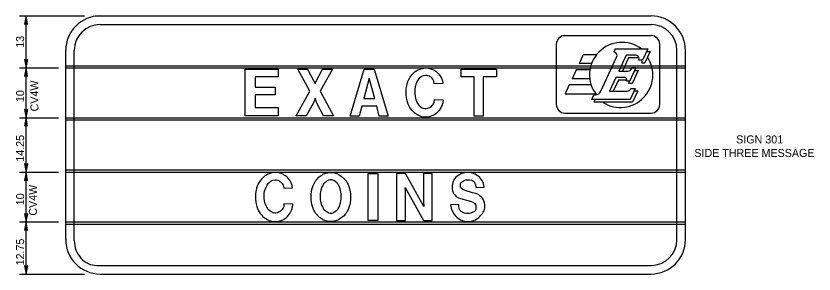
# Model space of a CAD drawing. Extents: x 319706 to 320346, y 1621790 to 1622121.
# Drawn here: x 319881.2 to 320020.8, y 1622067.9 to 1622113.1 of the extents above; entities that cross this region are included whole.
import ezdxf

# ---------------------------------------------------------------- set-up
doc = ezdxf.new("R2010")
doc.units = 0
for name, color, linetype in [('1', 7, 'Continuous'), ('40', 7, 'Continuous'), ('52', 7, 'Continuous'), ('SignPanel', 7, 'Continuous')]:
    doc.layers.add(name, color=color, linetype=linetype)

msp = doc.modelspace()

# ---------------------------------------------------------------- linework, layer by layer
at = {"layer": '1'}
for p, q in [((319881.84, 1622113.08), (319893.22, 1622113.08)), ((319882.98, 1622104), (319882.98, 1622113.08)), ((319881.84, 1622104), (319888.63, 1622104)), ((319882.98, 1622095.27), (319882.98, 1622104)), ((319881.84, 1622095.27), (319888.63, 1622095.27)), ((319882.98, 1622085.75), (319882.98, 1622095.27)), ((319881.84, 1622085.75), (319888.63, 1622085.75)), ((319882.98, 1622077.02), (319882.98, 1622085.75)), ((319881.84, 1622077.02), (319888.63, 1622077.02)), ((319882.98, 1622067.91), (319882.98, 1622077.01)), ((319881.84, 1622067.91), (319893.22, 1622067.91))]:
    msp.add_line(p, q, dxfattribs=at)
at = {"layer": '40'}
msp.add_line((319936.28, 1622085.68), (319936.22, 1622085.68), dxfattribs=at)
for points in [[(319921.32, 1622095.58), (319921.32, 1622103.78), (319927.07, 1622103.78), (319927.07, 1622102.43), (319923.03, 1622102.43), (319923.03, 1622100.62), (319926.55, 1622100.62), (319926.55, 1622099.26), (319923.03, 1622099.26), (319923.03, 1622097.06), (319927.07, 1622097.06), (319927.07, 1622095.58), (319921.32, 1622095.58)], [(319930.23, 1622095.57), (319932.64, 1622099.9), (319930.53, 1622103.78), (319932.23, 1622103.78), (319933.34, 1622101.65), (319933.52, 1622101.19), (319933.7, 1622101.65), (319934.81, 1622103.78), (319936.57, 1622103.78), (319934.4, 1622099.9), (319936.75, 1622095.57), (319934.99, 1622095.57), (319933.81, 1622097.83), (319933.52, 1622098.67), (319933.23, 1622097.9), (319931.99, 1622095.57), (319930.23, 1622095.57)], [(319939.68, 1622095.55), (319942.14, 1622103.75), (319943.85, 1622103.75), (319946.31, 1622095.55), (319944.72, 1622095.55), (319944.31, 1622097.29), (319941.73, 1622097.29), (319941.26, 1622095.55), (319939.68, 1622095.55)], [(319955.92, 1622098.42), (319955.87, 1622097.9), (319955.75, 1622097.51), (319955.57, 1622097.13), (319955.4, 1622096.8), (319955.22, 1622096.54), (319955.1, 1622096.42), (319954.99, 1622096.29), (319954.87, 1622096.16), (319954.63, 1622095.96), (319954.46, 1622095.83), (319954.34, 1622095.77), (319954.1, 1622095.64), (319953.93, 1622095.57), (319953.69, 1622095.51), (319953.46, 1622095.45), (319952.99, 1622095.38), (319952.7, 1622095.38), (319952.23, 1622095.45), (319952.05, 1622095.51), (319951.82, 1622095.57), (319951.58, 1622095.7), (319951.35, 1622095.83), (319951.23, 1622095.9), (319951.05, 1622096.03), (319950.76, 1622096.29), (319950.52, 1622096.54), (319950.29, 1622096.8), (319950.11, 1622097.06), (319949.94, 1622097.39), (319949.82, 1622097.64), (319949.7, 1622098.03), (319949.59, 1622098.48), (319949.53, 1622098.81), (319949.47, 1622099.26), (319949.47, 1622099.84), (319949.47, 1622100.29), (319949.53, 1622100.62), (319949.59, 1622100.87), (319949.64, 1622101.2), (319949.76, 1622101.59), (319949.94, 1622101.97), (319950.17, 1622102.36), (319950.47, 1622102.75), (319950.82, 1622103.14), (319951.05, 1622103.33), (319951.35, 1622103.52), (319951.58, 1622103.65), (319952.11, 1622103.85), (319952.34, 1622103.91), (319952.81, 1622103.98), (319953.05, 1622103.98), (319953.52, 1622103.91), (319953.75, 1622103.85), (319953.93, 1622103.78), (319954.22, 1622103.65), (319954.46, 1622103.52), (319954.63, 1622103.39), (319954.87, 1622103.2), (319955.04, 1622103.01), (319955.34, 1622102.68), (319955.46, 1622102.49), (319955.63, 1622102.17), (319955.81, 1622101.71), (319955.87, 1622101.26)], [(319959.09, 1622103.76), (319965.25, 1622103.76), (319965.25, 1622102.4), (319962.96, 1622102.4), (319962.96, 1622095.55), (319961.38, 1622095.55), (319961.38, 1622102.4), (319959.09, 1622102.4), (319959.09, 1622103.76)], [(319954.34, 1622101.2), (319954.28, 1622101.65), (319954.22, 1622101.78), (319954.1, 1622102.04), (319953.93, 1622102.23), (319953.81, 1622102.36), (319953.69, 1622102.43), (319953.52, 1622102.55), (319953.34, 1622102.62), (319953.11, 1622102.68), (319952.93, 1622102.68), (319952.46, 1622102.62), (319952.17, 1622102.49), (319951.76, 1622102.17), (319951.64, 1622102.04), (319951.46, 1622101.78), (319951.29, 1622101.39), (319951.17, 1622101.13), (319951.11, 1622100.87), (319951.05, 1622100.68), (319950.99, 1622100.29), (319950.99, 1622099.97), (319950.99, 1622099.9), (319950.99, 1622099.58), (319950.99, 1622099.39), (319951.05, 1622099), (319951.11, 1622098.68), (319951.17, 1622098.42), (319951.29, 1622098.16), (319951.4, 1622097.9), (319951.64, 1622097.51), (319951.99, 1622097.19), (319952.28, 1622097), (319952.46, 1622096.93), (319952.81, 1622096.87), (319952.99, 1622096.87), (319953.28, 1622096.93), (319953.58, 1622097.06), (319953.81, 1622097.19), (319954.05, 1622097.45), (319954.22, 1622097.71), (319954.34, 1622097.97), (319954.4, 1622098.48)], [(319943.02, 1622102.2), (319942.08, 1622098.65), (319943.96, 1622098.65), (319943.02, 1622102.2)], [(319955.87, 1622101.26), (319954.34, 1622101.2)], [(319954.4, 1622098.48), (319955.92, 1622098.42)], [(319929.58, 1622082.97), (319929.52, 1622083.42), (319929.34, 1622083.88), (319929.16, 1622084.2), (319929.04, 1622084.39), (319928.75, 1622084.72), (319928.57, 1622084.91), (319928.33, 1622085.1), (319928.15, 1622085.23), (319927.92, 1622085.36), (319927.62, 1622085.49), (319927.44, 1622085.56), (319927.2, 1622085.62), (319926.73, 1622085.69), (319926.49, 1622085.69), (319926.02, 1622085.62), (319925.78, 1622085.56), (319925.25, 1622085.36), (319925.01, 1622085.23), (319924.71, 1622085.04), (319924.48, 1622084.85), (319924.12, 1622084.46), (319923.82, 1622084.07), (319923.59, 1622083.68), (319923.41, 1622083.29), (319923.29, 1622082.91), (319923.23, 1622082.58), (319923.17, 1622082.32), (319923.11, 1622082), (319923.11, 1622081.55), (319923.11, 1622080.97), (319923.17, 1622080.52), (319923.23, 1622080.19), (319923.35, 1622079.74), (319923.47, 1622079.35), (319923.59, 1622079.1), (319923.77, 1622078.77), (319923.94, 1622078.51), (319924.18, 1622078.25), (319924.42, 1622078), (319924.71, 1622077.74), (319924.89, 1622077.61), (319925.01, 1622077.54), (319925.25, 1622077.41), (319925.49, 1622077.28), (319925.72, 1622077.22), (319925.9, 1622077.16), (319926.37, 1622077.09), (319926.67, 1622077.09), (319927.15, 1622077.16), (319927.38, 1622077.22), (319927.62, 1622077.28), (319927.8, 1622077.35), (319928.04, 1622077.48), (319928.15, 1622077.54), (319928.33, 1622077.67), (319928.57, 1622077.87), (319928.69, 1622078), (319928.8, 1622078.13), (319928.92, 1622078.25), (319929.1, 1622078.51), (319929.28, 1622078.84), (319929.46, 1622079.22), (319929.58, 1622079.61), (319929.63, 1622080.13)], [(319932.84, 1622081.36), (319932.84, 1622081.55), (319932.84, 1622081.87), (319932.9, 1622082.32), (319932.96, 1622082.71), (319933.08, 1622083.04), (319933.2, 1622083.42), (319933.37, 1622083.75), (319933.49, 1622084), (319933.61, 1622084.2), (319933.79, 1622084.39), (319934.2, 1622084.84), (319934.26, 1622084.91), (319934.44, 1622085.04), (319934.62, 1622085.17), (319934.8, 1622085.3), (319934.91, 1622085.36), (319935.21, 1622085.49), (319935.45, 1622085.56), (319935.69, 1622085.62), (319936.28, 1622085.68)], [(319936.22, 1622085.68), (319936.52, 1622085.68), (319936.93, 1622085.62), (319937.17, 1622085.56), (319937.35, 1622085.49), (319937.76, 1622085.3), (319938.12, 1622085.04), (319938.41, 1622084.78), (319938.77, 1622084.39), (319938.95, 1622084.2), (319939.06, 1622084), (319939.18, 1622083.75), (319939.3, 1622083.55), (319939.42, 1622083.23), (319939.54, 1622082.84), (319939.6, 1622082.58), (319939.66, 1622082.32), (319939.72, 1622081.94), (319939.72, 1622081.74), (319939.72, 1622081.36)], [(319942.84, 1622077.3), (319942.84, 1622085.5), (319944.5, 1622085.5), (319944.5, 1622077.3), (319942.84, 1622077.3)], [(319947.8, 1622085.49), (319947.8, 1622077.29), (319949.34, 1622077.29), (319949.34, 1622082.39), (319949.28, 1622083.04), (319952.48, 1622077.29), (319954.02, 1622077.29), (319954.02, 1622085.49), (319952.48, 1622085.49), (319952.48, 1622080.65), (319952.54, 1622079.74), (319949.34, 1622085.49), (319947.8, 1622085.49)], [(319962.08, 1622085.04), (319961.9, 1622085.17), (319961.78, 1622085.24), (319961.54, 1622085.37), (319961.25, 1622085.5), (319961.07, 1622085.56), (319960.89, 1622085.62), (319960.42, 1622085.69), (319960.18, 1622085.69), (319960.06, 1622085.69), (319959.65, 1622085.62), (319959.41, 1622085.56), (319959.05, 1622085.43), (319958.82, 1622085.3), (319958.7, 1622085.24), (319958.52, 1622085.11), (319958.34, 1622084.98)], [(319928.09, 1622080.19), (319928.04, 1622079.68), (319927.92, 1622079.42), (319927.74, 1622079.16), (319927.5, 1622078.9), (319927.26, 1622078.77), (319926.97, 1622078.64), (319926.67, 1622078.58), (319926.49, 1622078.58), (319926.14, 1622078.64), (319925.96, 1622078.71), (319925.66, 1622078.9), (319925.31, 1622079.22), (319925.07, 1622079.61), (319924.95, 1622079.87), (319924.83, 1622080.13), (319924.77, 1622080.39), (319924.71, 1622080.71), (319924.65, 1622081.1), (319924.65, 1622081.29), (319924.65, 1622081.61), (319924.65, 1622081.68), (319924.65, 1622082), (319924.71, 1622082.39), (319924.77, 1622082.58), (319924.83, 1622082.84), (319924.95, 1622083.1), (319925.13, 1622083.49), (319925.31, 1622083.75), (319925.43, 1622083.88), (319925.84, 1622084.2), (319926.14, 1622084.33), (319926.61, 1622084.39), (319926.79, 1622084.39), (319927.03, 1622084.33), (319927.2, 1622084.26), (319927.38, 1622084.13), (319927.5, 1622084.07), (319927.62, 1622083.94), (319927.8, 1622083.75), (319927.92, 1622083.49), (319927.98, 1622083.36), (319928.04, 1622082.91)], [(319938.12, 1622081.48), (319938.12, 1622081.61), (319938.12, 1622081.94), (319938.06, 1622082.26), (319938, 1622082.58), (319937.88, 1622082.97), (319937.76, 1622083.29), (319937.52, 1622083.68), (319937.35, 1622083.87), (319937.05, 1622084.13), (319936.81, 1622084.26), (319936.63, 1622084.33), (319936.46, 1622084.39), (319936.34, 1622084.39), (319936.16, 1622084.39), (319935.92, 1622084.33), (319935.63, 1622084.2), (319935.45, 1622084.07), (319935.33, 1622084), (319935.21, 1622083.87), (319935.09, 1622083.75), (319935.03, 1622083.68), (319934.86, 1622083.36), (319934.68, 1622083.04), (319934.62, 1622082.78), (319934.56, 1622082.58), (319934.5, 1622082.32), (319934.44, 1622082.07), (319934.44, 1622081.87), (319934.44, 1622081.61), (319934.44, 1622081.48)], [(319958.34, 1622084.98), (319958.1, 1622084.79), (319957.81, 1622084.4), (319957.63, 1622083.94), (319957.51, 1622083.43), (319957.51, 1622082.85), (319957.57, 1622082.46), (319957.75, 1622082.01), (319957.99, 1622081.75), (319958.22, 1622081.49), (319958.64, 1622081.23), (319958.99, 1622081.1), (319960.89, 1622080.58), (319961.19, 1622080.46), (319961.48, 1622080.26), (319961.66, 1622079.94), (319961.66, 1622079.62), (319961.66, 1622079.42)], [(319958.94, 1622083.36), (319958.94, 1622083.56), (319958.99, 1622083.82), (319959.17, 1622084.01), (319959.47, 1622084.2), (319959.71, 1622084.33), (319959.88, 1622084.4), (319960.18, 1622084.4), (319960.54, 1622084.4), (319960.89, 1622084.33), (319961.13, 1622084.2), (319961.31, 1622084.07), (319961.48, 1622083.82), (319961.6, 1622083.56), (319961.66, 1622083.04)], [(319961.66, 1622083.04), (319963.08, 1622083.1), (319963.03, 1622083.43), (319962.97, 1622083.75), (319962.85, 1622084.07), (319962.73, 1622084.27), (319962.55, 1622084.59), (319962.37, 1622084.79), (319962.08, 1622085.04)], [(319928.04, 1622082.91), (319929.58, 1622082.97)], [(319963.03, 1622078.9), (319963.08, 1622078.97), (319963.14, 1622079.23), (319963.2, 1622079.55), (319963.2, 1622079.87), (319963.2, 1622080.07), (319963.14, 1622080.33), (319963.03, 1622080.71), (319962.97, 1622080.91), (319962.79, 1622081.17), (319962.61, 1622081.42), (319962.43, 1622081.56), (319962.19, 1622081.75), (319961.84, 1622081.94), (319961.37, 1622082.07), (319961.07, 1622082.14), (319959.77, 1622082.52), (319959.35, 1622082.72), (319959.17, 1622082.85), (319959.05, 1622082.98), (319958.94, 1622083.17), (319958.94, 1622083.36)], [(319939.72, 1622081.36), (319939.72, 1622080.9), (319939.66, 1622080.32), (319939.6, 1622080.06), (319939.48, 1622079.74), (319939.36, 1622079.35), (319939.24, 1622079.09), (319939.12, 1622078.9), (319938.95, 1622078.58), (319938.77, 1622078.38), (319938.59, 1622078.12), (319938.29, 1622077.87), (319938.12, 1622077.74), (319937.94, 1622077.61), (319937.64, 1622077.41), (319937.35, 1622077.28), (319937.17, 1622077.22), (319936.81, 1622077.15), (319936.46, 1622077.09), (319936.34, 1622077.09), (319936.04, 1622077.09), (319935.63, 1622077.15), (319935.45, 1622077.22), (319935.21, 1622077.28), (319935.09, 1622077.35), (319934.91, 1622077.41), (319934.8, 1622077.48), (319934.62, 1622077.61), (319934.32, 1622077.8), (319934.2, 1622077.93), (319933.73, 1622078.45), (319933.61, 1622078.58), (319933.43, 1622078.9), (319933.31, 1622079.09), (319933.2, 1622079.35), (319933.08, 1622079.74), (319933.02, 1622079.93), (319932.96, 1622080.19), (319932.9, 1622080.45), (319932.84, 1622080.84), (319932.84, 1622081.16), (319932.84, 1622081.36)], [(319934.44, 1622081.48), (319934.44, 1622081.36), (319934.44, 1622081.1), (319934.44, 1622080.9), (319934.5, 1622080.64), (319934.56, 1622080.39), (319934.62, 1622080.19), (319934.68, 1622079.93), (319934.86, 1622079.61), (319935.03, 1622079.29), (319935.09, 1622079.22), (319935.21, 1622079.09), (319935.33, 1622078.96), (319935.45, 1622078.9), (319935.63, 1622078.77), (319935.92, 1622078.64), (319936.16, 1622078.58), (319936.34, 1622078.58)], [(319936.34, 1622078.58), (319936.46, 1622078.58), (319936.63, 1622078.64), (319936.81, 1622078.71), (319937.05, 1622078.84), (319937.35, 1622079.09), (319937.52, 1622079.29), (319937.76, 1622079.68), (319937.88, 1622080), (319938, 1622080.39), (319938.06, 1622080.71), (319938.12, 1622081.03), (319938.12, 1622081.36), (319938.12, 1622081.48)], [(319929.63, 1622080.13), (319928.09, 1622080.19)], [(319958.7, 1622079.87), (319958.7, 1622080.07), (319957.22, 1622080)], [(319957.22, 1622080), (319957.28, 1622079.74), (319957.33, 1622079.49), (319957.39, 1622079.23), (319957.45, 1622079.1), (319957.51, 1622078.97), (319957.63, 1622078.77), (319957.75, 1622078.52), (319957.81, 1622078.45), (319958.05, 1622078.13), (319958.34, 1622077.87), (319958.64, 1622077.61), (319958.76, 1622077.55), (319958.99, 1622077.42), (319959.11, 1622077.35), (319959.29, 1622077.29), (319959.41, 1622077.23), (319959.65, 1622077.16), (319960.06, 1622077.1), (319960.24, 1622077.1), (319960.42, 1622077.1), (319960.83, 1622077.16), (319961.13, 1622077.23), (319961.31, 1622077.29), (319961.6, 1622077.42), (319961.84, 1622077.55), (319962.02, 1622077.68), (319962.19, 1622077.81), (319962.31, 1622077.94), (319962.49, 1622078.13), (319962.61, 1622078.26), (319962.79, 1622078.52), (319962.91, 1622078.71), (319963.03, 1622078.9)], [(319961.01, 1622078.65), (319960.77, 1622078.58), (319960.48, 1622078.52), (319960.18, 1622078.52), (319960, 1622078.52), (319959.65, 1622078.58), (319959.29, 1622078.71), (319959.11, 1622078.84), (319958.94, 1622079.03), (319958.82, 1622079.23), (319958.76, 1622079.42), (319958.7, 1622079.68), (319958.7, 1622079.87)], [(319961.66, 1622079.42), (319961.66, 1622079.23), (319961.54, 1622078.97), (319961.42, 1622078.84), (319961.01, 1622078.65)]]:
    msp.add_lwpolyline(points, dxfattribs=at)
at = {"layer": '52'}
for p, q in [((319882.98, 1622113.08), (319882.7, 1622111.63)), ((319883.25, 1622111.63), (319882.98, 1622113.08)), ((319882.7, 1622111.63), (319882.98, 1622111.74)), ((319882.98, 1622111.74), (319883.25, 1622111.63)), ((319882.98, 1622105.34), (319882.71, 1622105.45)), ((319882.71, 1622105.45), (319882.98, 1622104)), ((319882.98, 1622104), (319883.26, 1622105.45)), ((319883.26, 1622105.45), (319882.98, 1622105.34)), ((319882.98, 1622104), (319882.7, 1622102.55)), ((319883.25, 1622102.55), (319882.98, 1622104)), ((319882.7, 1622102.55), (319882.98, 1622102.66)), ((319882.98, 1622102.66), (319883.25, 1622102.55)), ((319882.98, 1622096.61), (319882.71, 1622096.72)), ((319882.71, 1622096.72), (319882.98, 1622095.27)), ((319882.98, 1622095.27), (319883.26, 1622096.72)), ((319883.26, 1622096.72), (319882.98, 1622096.61)), ((319882.98, 1622095.27), (319882.7, 1622093.82)), ((319883.25, 1622093.82), (319882.98, 1622095.27)), ((319882.7, 1622093.82), (319882.98, 1622093.93)), ((319882.98, 1622093.93), (319883.25, 1622093.82)), ((319882.98, 1622087.09), (319882.71, 1622087.2)), ((319882.71, 1622087.2), (319882.98, 1622085.75)), ((319882.98, 1622085.75), (319883.26, 1622087.2)), ((319883.26, 1622087.2), (319882.98, 1622087.09)), ((319882.98, 1622085.75), (319882.7, 1622084.3)), ((319883.25, 1622084.3), (319882.98, 1622085.75)), ((319882.7, 1622084.3), (319882.98, 1622084.41)), ((319882.98, 1622084.41), (319883.25, 1622084.3)), ((319882.98, 1622078.36), (319882.71, 1622078.47)), ((319882.71, 1622078.47), (319882.98, 1622077.02)), ((319882.98, 1622077.02), (319883.26, 1622078.47)), ((319883.26, 1622078.47), (319882.98, 1622078.36)), ((319882.98, 1622077.02), (319882.7, 1622075.57)), ((319883.25, 1622075.57), (319882.98, 1622077.02)), ((319882.7, 1622075.57), (319882.98, 1622075.68)), ((319882.98, 1622075.68), (319883.25, 1622075.57)), ((319882.98, 1622069.25), (319882.71, 1622069.36)), ((319882.71, 1622069.36), (319882.98, 1622067.91)), ((319882.98, 1622067.91), (319883.26, 1622069.36)), ((319883.26, 1622069.36), (319882.98, 1622069.25))]:
    msp.add_line(p, q, dxfattribs=at)
at = {"layer": 'SignPanel'}
for p, q in [((319895.05, 1622113.08), (319992.3, 1622113.08)), ((319895.93, 1622111.57), (319992.3, 1622111.57)), ((319976.83, 1622109.64), (319992.3, 1622109.64)), ((319975.74, 1622097.59), (319975.74, 1622108.14)), ((319993.81, 1622097.59), (319993.81, 1622108.14)), ((319889.91, 1622073.93), (319889.91, 1622107.06)), ((319891.41, 1622073.77), (319891.41, 1622107.06)), ((319986.02, 1622107.31), (319985.76, 1622106.76)), ((319986.02, 1622107.31), (319991.72, 1622107.31)), ((319991.72, 1622107.31), (319990.81, 1622105.34)), ((319992.14, 1622106.85), (319991.22, 1622104.87)), ((319991.5, 1622106.85), (319992.14, 1622106.85)), ((319996.82, 1622073.93), (319996.82, 1622107.06)), ((319998.33, 1622073.93), (319998.33, 1622107.06)), ((319980.43, 1622106.3), (319979.71, 1622104.74)), ((319982.76, 1622106.3), (319980.43, 1622106.3)), ((319983.54, 1622099.91), (319986.28, 1622105.85)), ((319987.95, 1622106.2), (319986.67, 1622103.43)), ((319988.37, 1622105.74), (319987.3, 1622103.43)), ((319989.66, 1622106.2), (319987.95, 1622106.2)), ((319990.18, 1622105.74), (319988.37, 1622105.74)), ((319990.81, 1622105.34), (319990.14, 1622105.34)), ((319889.91, 1622104.37), (319998.33, 1622104.37)), ((319889.91, 1622104), (319998.33, 1622104)), ((319979.21, 1622103.65), (319978.49, 1622102.1)), ((319981.6, 1622103.65), (319979.21, 1622103.65)), ((319981.88, 1622104.74), (319979.71, 1622104.74)), ((319989.63, 1622104.03), (319988.57, 1622101.72)), ((319988.96, 1622104.03), (319988.87, 1622103.83)), ((319988.96, 1622104.03), (319989.63, 1622104.03)), ((319990.67, 1622104.87), (319991.22, 1622104.87)), ((319986.16, 1622102.32), (319985.05, 1622099.92)), ((319987.7, 1622102.32), (319986.16, 1622102.32)), ((319986.67, 1622103.43), (319988.28, 1622103.43)), ((319990.05, 1622103.56), (319988.99, 1622101.25)), ((319989.42, 1622103.56), (319990.05, 1622103.56)), ((319977.99, 1622101.01), (319977.27, 1622099.45)), ((319981.82, 1622101.01), (319977.99, 1622101.01)), ((319981.58, 1622102.1), (319978.49, 1622102.1)), ((319986.58, 1622101.85), (319985.68, 1622099.92)), ((319988.05, 1622101.85), (319986.58, 1622101.85)), ((319988, 1622101.72), (319988.57, 1622101.72)), ((319988.99, 1622101.25), (319988.43, 1622101.25)), ((319977.27, 1622099.45), (319982.62, 1622099.45)), ((319985.05, 1622099.92), (319988.12, 1622099.92)), ((319989.54, 1622100.41), (319988.63, 1622098.44)), ((319988.87, 1622100.41), (319989.54, 1622100.41)), ((319989.96, 1622099.95), (319989.04, 1622097.97)), ((319989.32, 1622099.95), (319989.96, 1622099.95)), ((319981.92, 1622098.44), (319982.3, 1622099.26)), ((319988.63, 1622098.44), (319981.92, 1622098.44)), ((319982.3, 1622099.26), (319982.58, 1622099.26)), ((319982.34, 1622097.97), (319982.55, 1622098.44)), ((319989.04, 1622097.97), (319982.34, 1622097.97)), ((319889.91, 1622095.27), (319998.33, 1622095.27)), ((319977.24, 1622096.09), (319992.3, 1622096.09)), ((319889.91, 1622094.89), (319998.33, 1622094.89)), ((319889.91, 1622086.16), (319998.33, 1622086.16)), ((319889.91, 1622085.75), (319998.33, 1622085.75)), ((319889.91, 1622077.02), (319998.33, 1622077.02)), ((319889.91, 1622076.64), (319998.33, 1622076.64)), ((319895.36, 1622069.41), (319992.3, 1622069.41)), ((319895.93, 1622067.91), (319992.3, 1622067.91))]:
    msp.add_line(p, q, dxfattribs=at)
for centre, radius, start, end in [((319895.93, 1622107.06), 6.02, 90, 180), ((319992.3, 1622107.06), 6.02, 0, 90), ((319895.93, 1622107.06), 4.52, 90, 180), ((319992.3, 1622107.06), 4.52, 0, 90), ((319977.24, 1622108.14), 1.51, 90, 180), ((319992.3, 1622108.14), 1.51, 0, 90), ((319987.21, 1622102.79), 5.67, 52.9547, 218.1763), ((319986.94, 1622102.74), 5.67, 238.1578, 33.3171), ((319977.24, 1622097.59), 1.51, 180, 270), ((319992.3, 1622097.59), 1.51, 270, 360), ((319895.93, 1622073.93), 6.02, 180, 270), ((319992.3, 1622073.93), 4.52, 270, 0), ((319992.3, 1622073.93), 6.02, 270, 0)]:
    msp.add_arc(centre, radius, start, end, dxfattribs=at)
for centre, major_axis, start_param, end_param in [((319985.78, 1622106.14), (0, 0.623), 4.241328, 6.314398), ((319989.66, 1622105.61), (0, 0.592), 4.227342, 6.283185), ((319990.2, 1622105.14), (0, 0.592), 4.227342, 5.041732), ((319988.27, 1622104.17), (0, 0.74), 3.141593, 4.241405), ((319987.7, 1622101.93), (0, 0.389), 4.144801, 6.283185), ((319987.96, 1622101.53), (0, 0.592), 4.227342, 5.041732), ((319982.58, 1622100.45), (0, 1.18), 3.141593, 4.241135), ((319988.12, 1622100.84), (0, 0.924), 3.141593, 4.232591), ((319895.36, 1622073.77), (0, 4.36), 1.570796, 3.141593)]:
    msp.add_ellipse(centre, major_axis=major_axis, ratio=0.906668, start_param=start_param, end_param=end_param, dxfattribs=at)

# ---------------------------------------------------------------- texts
at = {"layer": '1'}
for s, p in [('13', (319882.63, 1622107.51)), ('CV4W', (319885.14, 1622096.37)), ('10', (319882.63, 1622098.01)), ('14.25', (319882.63, 1622087.57)), ('CV4W', (319884.87, 1622078.12)), ('10', (319882.63, 1622079.95)), ('12.75', (319882.63, 1622069.42))]:
    msp.add_text(s, height=1.4, rotation=90, dxfattribs=at).set_placement(p)
msp.add_text('SIDE THREE MESSAGE', height=1.4, dxfattribs=at).set_placement((319999.87, 1622088.4))
at = {"layer": '40'}
msp.add_text('SIGN 301', height=1.4, dxfattribs=at).set_placement((320007.19, 1622090.77))

doc.saveas('drawing.dxf')
